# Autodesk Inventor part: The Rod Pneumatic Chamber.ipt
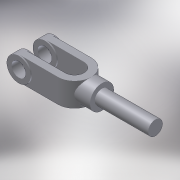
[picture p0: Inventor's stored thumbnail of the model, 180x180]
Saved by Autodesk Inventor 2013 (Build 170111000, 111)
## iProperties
Created: 2005-03
Part Number: The Rod Pneumatic Chamber.ipt
Material: Steel, Mild
Document SubType Name: Modeling
Designer: salex
Manufacturer: Standard
Standards Organization: Custom
Density: 7.86 g/cm^3
Mass: 167.426 g
Surface Area: 89.3279 cm^2
Volume: 21.301 cm^3
Author: salex
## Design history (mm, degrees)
derived "PNEVMOCAM_SHTOCK.iam"
body "Solid1"
node "PNEVMOCAM_SHTOCK PART2.ipt:1"
node "PNEVMOCAM_SHTOCK PART1.ipt:1"
